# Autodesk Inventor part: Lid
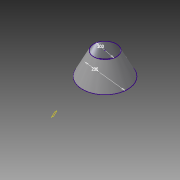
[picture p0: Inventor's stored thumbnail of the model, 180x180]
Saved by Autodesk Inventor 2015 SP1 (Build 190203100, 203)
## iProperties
Created: 2013-06
Part Number: Lid
Material: Steel, Mild
Document SubType Name: Sheet Metal
Designer: 1103005
Density: 7.86 g/cm^3
Sheet Metal Rule: Default_mm
Appearance: Steel
Sheet Metal Width: 222.263 mm
Sheet Metal Length: 432.356 mm
Sheet Metal Area: 96096.638 mm^2
Flat Pattern Width: 22.2263 cm
Flat Pattern Length: 43.2356 cm
Flat Pattern Area: 960.966 cm^2
Author: 1103005
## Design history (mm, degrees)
sketch "Sketch1"
  geometry: C1 r 100 at (0, 0); 1 further point
  constraints: 1 centre point, 1 coincident
  dimensions: "d0" = 200 diameter of C1
workplane "Work Plane1"
sketch "Sketch2"
  geometry: C1 r 50 at (0, 0); 1 further point
  constraints: 1 centre point, 1 coincident
  dimensions: "d2" = 100 diameter of C1
sketch "Sketch5"
  geometry: L1 (0, 0)-(0, 100); L2 (50, 100)-(100, 0)
  constraints: 4 end point, 2 horizontal alignment, 1 vertical
  dimensions: "d27" = 100 distance of L1.start L1.end; "d28" = 200 diameter of L2.end L1; "d29" = 100 vertical distance of L2.start L1
feature "Contour Roll1" sketch "Sketch5" dims "d31" = 62.8144, "d32" = 467.73702, "d33" = 74.46334, "Thickness" = 1.2 (derived)
workplane "Work Plane2"
sketch "Sketch6"
  geometry: C1 r 1.75 at (0, -357.096) reference; 2 further points
  constraints: 1 coincident
hole "Hole3" sketch "Sketch6" at (0, -357.096) diameter "d34" = 3.5; stored, may be unused: countersink angle "d38" = 90 deg, drill point angle "d40" = 118 deg; dims "d35" = 6, "d36" = 4, "d37" = 2, "d39" = 1.2 (= Thickness)
pattern_circular "Circular Pattern2" dims angle "d42" = 360 deg
body "Solid1"
node "Reference2"
feature "Definition1"
other parameters: "BendRadius" = 1.2 (= Thickness), "BendReliefWidth" = 1.2 (= Thickness), "BendReliefDepth" = 0.6 (= 0.5 x Thickness), "CornerReliefSize" = 4.8 (= 4 x Thickness), "SeamGap" = 0.01, "MinimumRemnant" = 2.4 (= 2 x Thickness), "TransitionRadius" = 1.2 (= BendRadius), "JacobiRadiusSize" = 1.2 (= BendRadius), "GapSize" = 1.2 (= Thickness), "d30" = 1.2 (= BendRadius), "BendRadius" = 1.2, "BendReliefDepth" = 0.6, "BendReliefWidth" = 1.2, "CornerReliefSize" = 4.8, "GapSize" = 1.2, "JacobiRadiusSize" = 1.2, "MinimumRemnant" = 2.4, "Thickness" = 1.2, "TransitionRadius" = 1.2
